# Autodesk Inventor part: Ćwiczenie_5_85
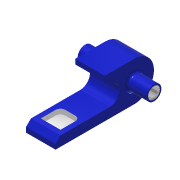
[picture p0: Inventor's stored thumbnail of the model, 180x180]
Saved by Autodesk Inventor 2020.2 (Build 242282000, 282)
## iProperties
Created: 2005-08
Part Number: Ćwiczenie_5_85
Document SubType Name: Modeling
Designer: F.Stasiak
Density: 1 g/cm^3
Material: Ogólny
Appearance: Niebieska — farba ścienna — lśniąca
Manager: www.cadconsulting.pl
Company: Fabian Stasiak CAD Consulting
Author: F.Stasiak
Subject: Zbiór ćwiczeń. Autodesk Inventor 2020. Kurs podstawowy
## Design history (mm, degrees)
sketch "Szkic1"
  geometry: L1 (-60, 20)-(-50, 20); L2 (-50, -20)-(-160, -20); L3 (-160, -20)-(-160, -40); L4 (-60, 40)-(-60, 20); L5 (-60, 40)-(0, 40); L6 (-160, -40)-(0, -40); C1 r 15 at (0, 0); A1 r 20 centre (-50, 0) between (-50, -20) and (-50, 20); A2 r 40 centre (0, 0) between (0, -40) and (0, 40); 1 further point
  constraints: 12 end point, 4 point on circle, 4 tangent, 3 centre point, 3 perpendicular, 2 parallel, 1 concentric, 1 horizontal
  dimensions: "d0" = 20 radius of A1; "d4" = 30 diameter of C1; "d5" = 0 distance of point (0, 0) C1.centre; "d6" = 40 radius of A2; "d7" = 200 dimension on A2 L3; "d31" = 20 distance of L2.end L3.end (= 0.5 x d6); "d32" = 20 distance from line of point (0, 0) L2; "d34" = 10 distance from line of L1.end L4; "d63" = 60 distance of L4.start L5.end
extrude "Wyciągnięcie proste1" new body sketch "Szkic1" stored distance "d8" = 60; taper "d9" = 0 deg
extrude "Wyciągnięcie proste2" join sketch "Szkic1" stored distance "d10" = 140; taper "d11" = 0 deg
sketch "Szkic2"
  geometry: C1 r 15 at (0, 0) reference
hole "Otwór1" sketch "Szkic2" at (0, 0) diameter "d21" = 20; stored, may be unused: countersink angle "d25" = 90 deg, drill point angle "d27" = 118 deg; dims "d22" = 6, "d23" = 4, "d24" = 2, "d26" = 8
node "Płaszczyzna konstrukcyjna3"
sketch "Szkic6"
  geometry: 1 further point
hole "Otwory2" sketch "Szkic6" at (0, 0) diameter "d50" = 20; stored, may be unused: countersink angle "d54" = 90 deg, drill point angle "d56" = 118 deg; dims "d51" = 6, "d52" = 4, "d53" = 2, "d55" = 40
fillet "Zaokrąglenie4" dims "d70" = 10
node "Bryła1"
node "Korpusy bryłowe"
node "Korpusy powierzchniowe"
fillet "Zaokrąglenie1" dims "d20" = 5
chamfer "Faza1" distance "d28" = 2; stored, may be unused: second distance "d29" = 2, angle "d30" = 45 deg
chamfer "Faza2" distance "d60" = 10; stored, may be unused: second distance "d61" = 2, angle "d62" = 45 deg
sketch "Szkic7"
  geometry: L1 (-90, 50)-(-50, 50); L2 (-50, 50)-(-50, 10); L3 (-50, 10)-(-90, 10); L4 (-90, 10)-(-90, 50)
  constraints: 8 end point, 2 parallel, 1 horizontal, 1 perpendicular
  dimensions: "d64" = 40 distance of L1.start L1.end; "d65" = 40 distance of L1.end L2.end
extrude "Wyciągnięcie proste3" cut sketch "Szkic7" distance "d68" = 10; taper "d69" = 0 deg
